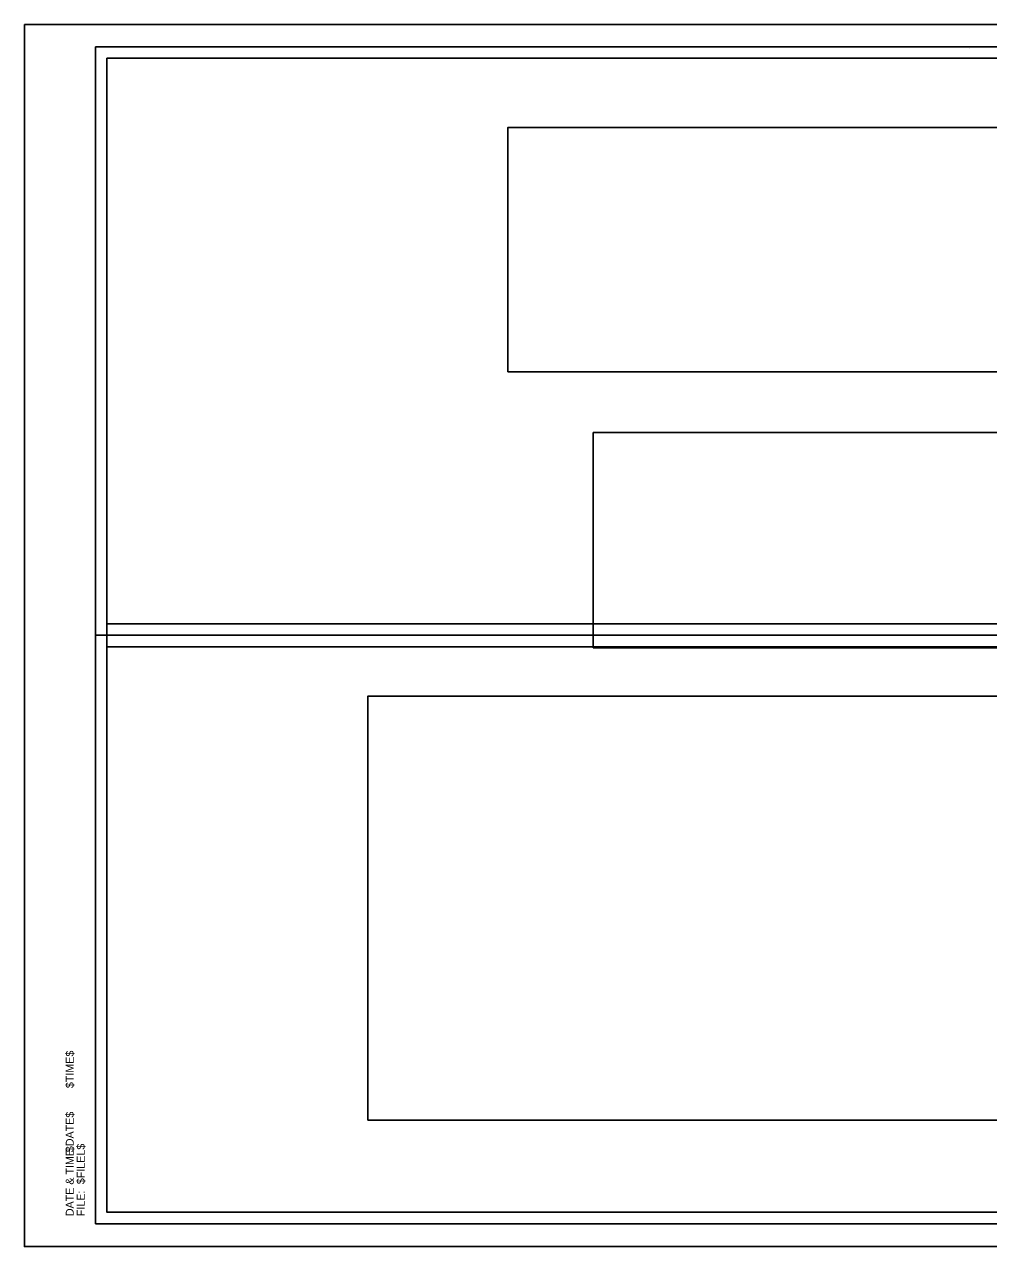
# Model space of a CAD drawing. Extents: x 1369904 to 1372237, y 380119 to 380332.
# Drawn here: x 1370903.6 to 1371071.9, y 380119.1 to 380332.4 of the extents above; entities that cross this region are included whole.
import ezdxf

# ---------------------------------------------------------------- set-up
doc = ezdxf.new("R2010")
doc.units = 0
for name, color, linetype in [('Default', 7, 'Continuous'), ('R_Border', 7, 'Continuous'), ('R_Border Notes', 7, 'Continuous'), ('R_Border Plan-Plan', 7, 'Continuous'), ('R_No Plot', 7, 'Continuous')]:
    doc.layers.add(name, color=color, linetype=linetype)

msp = doc.modelspace()

# ---------------------------------------------------------------- linework, layer by layer
at = {"layer": 'Default'}
for points in [[(1370987.93, 380271.73), (1371152.6, 380271.73), (1371152.6, 380314.39), (1370987.93, 380314.39)], [(1371002.88, 380223.6), (1371137.65, 380223.6), (1371137.65, 380261.16), (1371002.88, 380261.16)], [(1370963.52, 380141.11), (1371190.53, 380141.11), (1371190.53, 380215.12), (1370963.52, 380215.12)]]:
    msp.add_lwpolyline(points, close=True, dxfattribs=at)
at = {"layer": 'R_Border'}
for p, q in [((1370916, 380328.5), (1371232.18, 380328.5)), ((1370916, 380123.04), (1370916, 380328.5)), ((1371068.52, 380328.24), (1371068.52, 380328.24)), ((1371068.52, 380328.24), (1371068.52, 380328.24)), ((1370916, 380123.04), (1370916, 380123.04)), ((1371232.18, 380123.04), (1370916, 380123.04))]:
    msp.add_line(p, q, dxfattribs=at)
at = {"layer": 'R_Border Plan-Plan'}
msp.add_line((1370916, 380225.77), (1371232.18, 380225.77), dxfattribs=at)
at = {"layer": 'R_No Plot'}
for points in [[(1370903.6, 380332.4), (1371236.94, 380332.4), (1371236.94, 380119.06), (1370903.6, 380119.06)], [(1371230.18, 380227.77), (1370918, 380227.77), (1370918, 380326.5), (1371167.54, 380326.5), (1371167.54, 380316.62), (1371185.08, 380316.62), (1371209.18, 380316.62), (1371209.18, 380294.29), (1371230.18, 380294.29)], [(1370918, 380326.5), (1371167.54, 380326.5), (1371167.54, 380316.62), (1371185.08, 380316.62), (1371209.18, 380316.62), (1371209.18, 380294.29), (1371230.18, 380294.29), (1371230.18, 380125.04), (1370918, 380125.04)], [(1370918, 380223.77), (1371230.18, 380223.77), (1371230.18, 380125.04), (1370918, 380125.04)]]:
    msp.add_lwpolyline(points, close=True, dxfattribs=at)

# ---------------------------------------------------------------- texts
at = {"layer": 'R_Border Notes'}
for s, height, p in [('$TIME$', 1.397, (1370912.2, 380146.72)), ('$DATE$', 1.397, (1370912.2, 380135.54)), ('DATE & TIME:', 1.3968, (1370912.2, 380124.37)), ('$FILEL$', 1.397, (1370914.12, 380129.95)), ('FILE: ', 1.397, (1370914.12, 380124.37))]:
    msp.add_text(s, height=height, rotation=90, dxfattribs=at).set_placement(p)

doc.saveas('drawing.dxf')
